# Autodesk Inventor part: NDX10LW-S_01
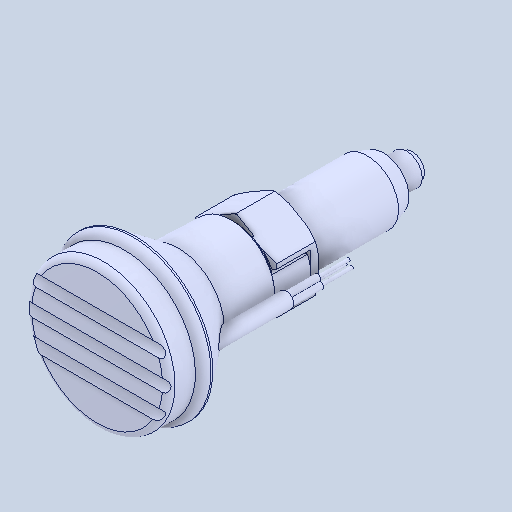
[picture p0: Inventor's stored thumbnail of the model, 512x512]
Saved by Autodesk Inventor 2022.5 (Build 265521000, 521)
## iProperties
Created: 2024-05
Part Number: NDX10LW-S_01
Material: 一般
Document SubType Name: Modeling
Designer: ImaoCorp
Density: 1 g/cm^3
Appearance: 既定
Author: ImaoCorp
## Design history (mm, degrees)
feature "NDX10LW-S_01"
node "ソリッド1"
